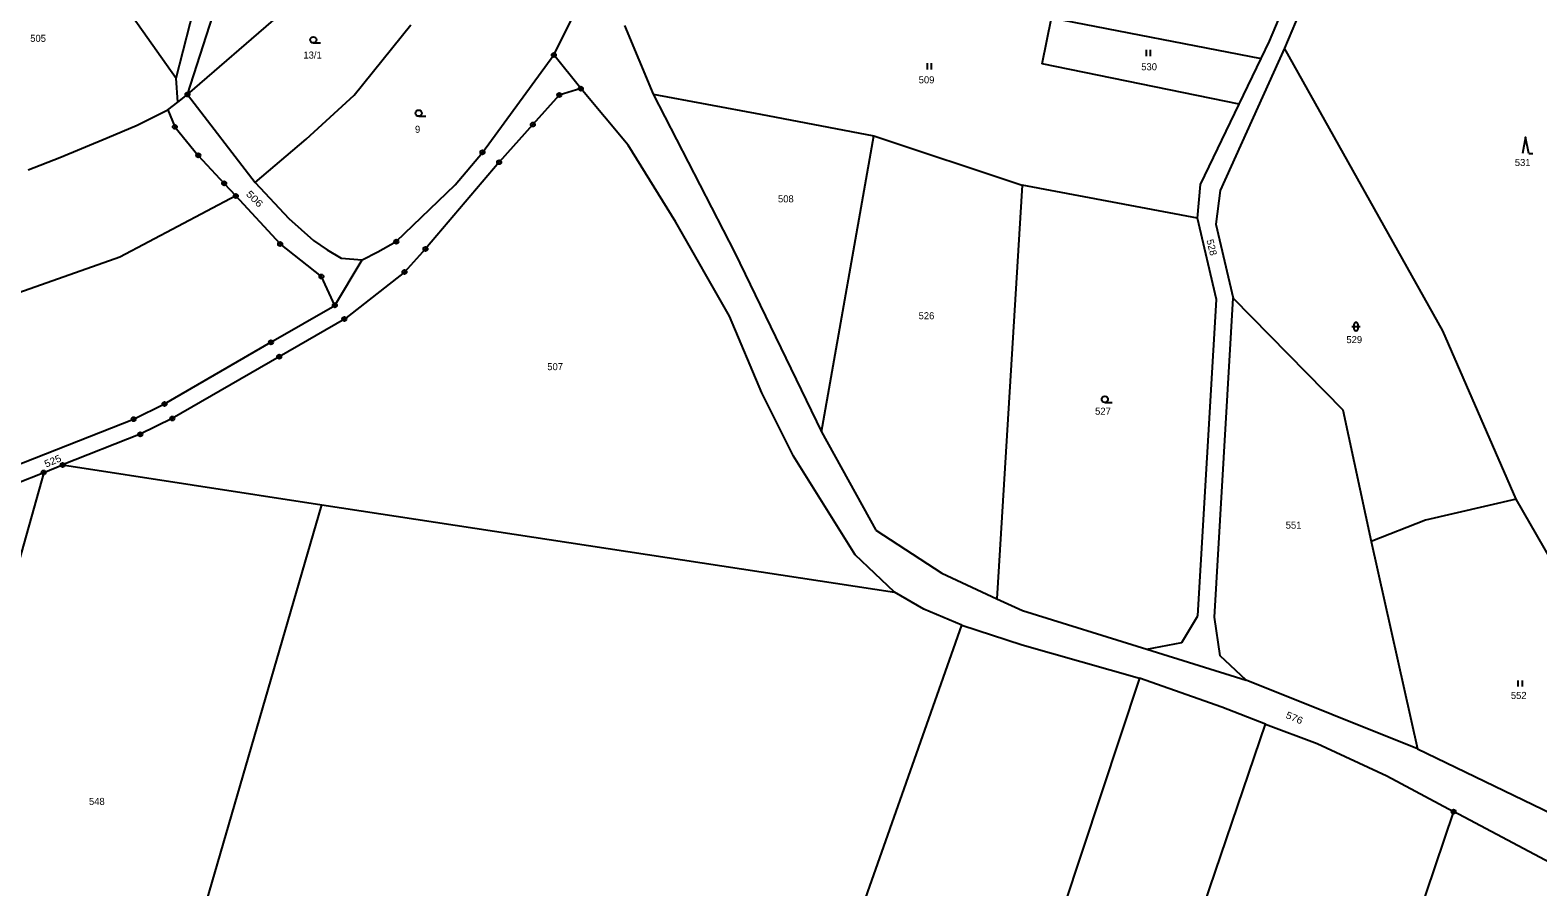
# Model space of a CAD drawing. Extents: x -719614 to -717765, y -1095834 to -1093862.
# Drawn here: x -718913.7 to -718549.9, y -1095578 to -1095371.4 of the extents above; entities that cross this region are included whole.
import ezdxf
from ezdxf.enums import TextEntityAlignment as Align

# ---------------------------------------------------------------- set-up
doc = ezdxf.new("R2010")
doc.units = 0
doc.header["$LTSCALE"] = 0.68
for name, color, linetype, lineweight in [('1', 7, 'Continuous', 25), ('3', 7, 'Continuous', 25), ('8', 7, 'Continuous', 25)]:
    doc.layers.add(name, color=color, linetype=linetype, lineweight=lineweight)
doc.layers.add('2', color=7, linetype='Continuous')

msp = doc.modelspace()

# ---------------------------------------------------------------- linework, layer by layer
at = {"layer": '1'}
for p, q in [((-718908.69, -1095340.19), (-718878.49, -1095383)), ((-718875.73, -1095386.91), (-718864.2, -1095351)), ((-718614.65, -1095374.04), (-718606.5, -1095354.9)), ((-718602.56, -1095355.86), (-718611.04, -1095375.76)), ((-718878.49, -1095383), (-718872.04, -1095357.83)), ((-718787.32, -1095377.39), (-718781.29, -1095365.38)), ((-718875.73, -1095386.91), (-718853.79, -1095367.97)), ((-718835.53, -1095387.04), (-718821.84, -1095370.12)), ((-718770.26, -1095370.31), (-718763.38, -1095386.82)), ((-718669.47, -1095379.53), (-718667.2, -1095368.41)), ((-718667.2, -1095368.41), (-718616.65, -1095378.21)), ((-718616.65, -1095378.21), (-718614.65, -1095374.04)), ((-718804.55, -1095400.87), (-718787.32, -1095377.39)), ((-718780.81, -1095385.51), (-718787.32, -1095377.39)), ((-718611.04, -1095375.76), (-718626.57, -1095410.1)), ((-718621.96, -1095389.26), (-718616.65, -1095378.21)), ((-718572.81, -1095443.92), (-718611.04, -1095375.76)), ((-718621.96, -1095389.26), (-718669.47, -1095379.53)), ((-718878.08, -1095388.77), (-718878.49, -1095383)), ((-718780.81, -1095385.51), (-718786, -1095387.04)), ((-718769.35, -1095399.14), (-718780.81, -1095385.51)), ((-718880.45, -1095390.65), (-718878.08, -1095388.77)), ((-718878.08, -1095388.77), (-718875.73, -1095386.91)), ((-718875.73, -1095386.91), (-718859.38, -1095408.13)), ((-718847.12, -1095397.66), (-718835.53, -1095387.04)), ((-718786, -1095387.04), (-718792.39, -1095394.17)), ((-718763.38, -1095386.82), (-718737.45, -1095391.68)), ((-718763.38, -1095386.82), (-718743.68, -1095425.09)), ((-718631.26, -1095408.66), (-718621.96, -1095389.26)), ((-718887.91, -1095394.28), (-718880.45, -1095390.65)), ((-718880.45, -1095390.65), (-718878.78, -1095394.72)), ((-718737.45, -1095391.68), (-718710.11, -1095396.88)), ((-718895.14, -1095397.39), (-718887.91, -1095394.28)), ((-718878.78, -1095394.72), (-718873.12, -1095401.61)), ((-718792.39, -1095394.17), (-718800.53, -1095403.26)), ((-718906.55, -1095402.14), (-718895.14, -1095397.39)), ((-718859.38, -1095408.13), (-718847.12, -1095397.66)), ((-718757.9, -1095417.72), (-718769.35, -1095399.14)), ((-718722.72, -1095468.25), (-718710.11, -1095396.88)), ((-718914.16, -1095405.09), (-718906.55, -1095402.14)), ((-718873.12, -1095401.61), (-718866.88, -1095408.36)), ((-718800.53, -1095403.26), (-718818.31, -1095424.18)), ((-718811.16, -1095408.71), (-718804.55, -1095400.87)), ((-718864.07, -1095411.4), (-718892.08, -1095426.15)), ((-718866.88, -1095408.36), (-718864.07, -1095411.4)), ((-718853.38, -1095422.98), (-718864.07, -1095411.4)), ((-718859.38, -1095408.13), (-718851.29, -1095416.82)), ((-718825.34, -1095422.41), (-718811.16, -1095408.71)), ((-718632.02, -1095416.73), (-718674.3, -1095408.79)), ((-718632.02, -1095416.73), (-718631.26, -1095408.66)), ((-718626.57, -1095410.1), (-718627.57, -1095418.19)), ((-718851.29, -1095416.82), (-718845.32, -1095422.11)), ((-718744.93, -1095440.4), (-718757.9, -1095417.72)), ((-718627.42, -1095436.36), (-718632.02, -1095416.73)), ((-718627.57, -1095418.19), (-718623.39, -1095436.01)), ((-718845.32, -1095422.11), (-718842.06, -1095424.37)), ((-718843.4, -1095430.82), (-718853.38, -1095422.98)), ((-718842.06, -1095424.37), (-718838.62, -1095426.36)), ((-718833.57, -1095426.8), (-718829.8, -1095424.89)), ((-718829.8, -1095424.89), (-718825.34, -1095422.41)), ((-718818.31, -1095424.18), (-718823.37, -1095429.75)), ((-718743.68, -1095425.09), (-718722.72, -1095468.25)), ((-718892.08, -1095426.15), (-718971.21, -1095454.09)), ((-718840.17, -1095437.78), (-718833.57, -1095426.8)), ((-718838.62, -1095426.36), (-718833.57, -1095426.8)), ((-718840.17, -1095437.78), (-718843.4, -1095430.82)), ((-718823.37, -1095429.75), (-718837.87, -1095441.08)), ((-718631.9, -1095512.66), (-718627.42, -1095436.36)), ((-718627.91, -1095513.02), (-718623.39, -1095436.01)), ((-718623.39, -1095436.01), (-718596.9, -1095463)), ((-718855.59, -1095446.7), (-718840.17, -1095437.78)), ((-718737.17, -1095458.92), (-718744.93, -1095440.4)), ((-718837.87, -1095441.08), (-718853.59, -1095450.16)), ((-718555.1, -1095484.57), (-718572.81, -1095443.92)), ((-718881.28, -1095461.56), (-718855.59, -1095446.7)), ((-718853.59, -1095450.16), (-718879.4, -1095465.08)), ((-718888.73, -1095465.23), (-718881.28, -1095461.56)), ((-718729.47, -1095474.16), (-718737.17, -1095458.92)), ((-718917.97, -1095476.77), (-718888.73, -1095465.23)), ((-718879.4, -1095465.08), (-718887.11, -1095468.89)), ((-718596.9, -1095463), (-718590.12, -1095494.76)), ((-718887.11, -1095468.89), (-718905.85, -1095476.29)), ((-718722.72, -1095468.25), (-718709.63, -1095492.03)), ((-718910.42, -1095478.1), (-718905.85, -1095476.29)), ((-718905.85, -1095476.29), (-718843.27, -1095485.87)), ((-718714.65, -1095497.99), (-718729.47, -1095474.16)), ((-718910.42, -1095478.1), (-718949.18, -1095616.11)), ((-718916.93, -1095480.67), (-718910.42, -1095478.1)), ((-718889.92, -1095646.28), (-718843.27, -1095485.87)), ((-718843.27, -1095485.87), (-718705.14, -1095506.99)), ((-718555.1, -1095484.57), (-718576.95, -1095489.6)), ((-718515.95, -1095552.63), (-718555.1, -1095484.57)), ((-718576.95, -1095489.6), (-718590.12, -1095494.76)), ((-718709.63, -1095492.03), (-718693.73, -1095502.36)), ((-718590.12, -1095494.76), (-718578.93, -1095544.76)), ((-718705.14, -1095506.99), (-718714.65, -1095497.99)), ((-718693.73, -1095502.36), (-718680.42, -1095508.56)), ((-718698.04, -1095511.07), (-718705.14, -1095506.99)), ((-718680.42, -1095508.56), (-718674.26, -1095511.42)), ((-718688.84, -1095514.91), (-718698.04, -1095511.07)), ((-718674.26, -1095511.42), (-718644.22, -1095520.71)), ((-718635.76, -1095519.11), (-718631.9, -1095512.66)), ((-718626.53, -1095522.3), (-718627.91, -1095513.02)), ((-718703.75, -1095557.1), (-718688.84, -1095514.91)), ((-718688.84, -1095514.91), (-718674.34, -1095519.63)), ((-718674.34, -1095519.63), (-718646, -1095527.74)), ((-718644.22, -1095520.71), (-718635.76, -1095519.11)), ((-718644.22, -1095520.71), (-718620.27, -1095528.22)), ((-718620.27, -1095528.22), (-718626.53, -1095522.3)), ((-718646, -1095527.74), (-718664.41, -1095583.31)), ((-718626.1, -1095534.71), (-718646, -1095527.74)), ((-718578.93, -1095544.76), (-718620.27, -1095528.22)), ((-718615.58, -1095538.8), (-718626.1, -1095534.71)), ((-718645.05, -1095625.35), (-718615.58, -1095538.8)), ((-718615.58, -1095538.8), (-718603.13, -1095543.49)), ((-718603.13, -1095543.49), (-718586.33, -1095551.23)), ((-718578.93, -1095544.76), (-718546.41, -1095560.42)), ((-718586.33, -1095551.23), (-718570.21, -1095559.91)), ((-718764.27, -1095728.35), (-718703.75, -1095557.1)), ((-718570.21, -1095559.91), (-718587.03, -1095609.31)), ((-718492.07, -1095601.38), (-718570.21, -1095559.91))]:
    msp.add_line(p, q, dxfattribs=at)
msp.add_lwpolyline([(-718710.11, -1095396.88), (-718674.3, -1095408.79), (-718680.42, -1095508.56)], dxfattribs=at)
at = {"layer": '3'}
for p, q in [((-718845.383, -1095374.49), (-718843.633, -1095374.49)), ((-718644.321, -1095377.64), (-718644.321, -1095376.14)), ((-718643.32, -1095377.64), (-718643.32, -1095376.14)), ((-718697.171, -1095380.9), (-718697.171, -1095379.4)), ((-718696.17, -1095380.9), (-718696.17, -1095379.4)), ((-718819.943, -1095392.17), (-718818.193, -1095392.17)), ((-718552.08, -1095401.18), (-718551.084, -1095401.18)), ((-718594.761, -1095442.911), (-718592.759, -1095442.911)), ((-718594.261, -1095442.411), (-718594.261, -1095443.412)), ((-718593.259, -1095443.412), (-718593.259, -1095442.411)), ((-718654.363, -1095461.18), (-718652.613, -1095461.18)), ((-718554.621, -1095529.74), (-718554.621, -1095528.24)), ((-718553.62, -1095529.74), (-718553.62, -1095528.24))]:
    msp.add_line(p, q, dxfattribs=at)
msp.add_lwpolyline([(-718552.08, -1095401.18), (-718552.83, -1095397.18), (-718553.58, -1095401.18)], dxfattribs=at)
for centre in [(-718845.3829, -1095373.7398), (-718819.9429, -1095391.4198), (-718654.3629, -1095460.4298)]:
    msp.add_circle(centre, 0.75, dxfattribs=at)
for centre, start, end in [((-718593.76, -1095442.4109), 0, 180), ((-718593.76, -1095443.4109), 180, 359.98789)]:
    msp.add_arc(centre, 0.5, start, end, dxfattribs=at)
at = {"layer": '8'}
for centre, radius in [((-718787.32, -1095377.3899), 0.5), ((-718787.32, -1095377.3899), 0.0303), ((-718780.81, -1095385.5099), 0.5), ((-718780.81, -1095385.5099), 0.0303), ((-718875.73, -1095386.9099), 0.5), ((-718875.73, -1095386.9099), 0.0303), ((-718786, -1095387.0399), 0.5), ((-718786, -1095387.0399), 0.0303), ((-718878.78, -1095394.7199), 0.5), ((-718878.78, -1095394.7199), 0.0303), ((-718792.39, -1095394.1699), 0.5), ((-718792.39, -1095394.1699), 0.0303), ((-718804.55, -1095400.8699), 0.5), ((-718873.12, -1095401.6099), 0.5), ((-718873.12, -1095401.6099), 0.0303), ((-718804.55, -1095400.8699), 0.0303), ((-718800.53, -1095403.2599), 0.5), ((-718800.53, -1095403.2599), 0.0303), ((-718866.88, -1095408.3599), 0.5), ((-718866.88, -1095408.3599), 0.0303), ((-718864.07, -1095411.3999), 0.5), ((-718864.07, -1095411.3999), 0.0303), ((-718825.34, -1095422.4099), 0.5), ((-718853.38, -1095422.9799), 0.5), ((-718853.38, -1095422.9799), 0.0303), ((-718825.34, -1095422.4099), 0.0303), ((-718818.31, -1095424.1799), 0.5), ((-718818.31, -1095424.1799), 0.0303), ((-718823.37, -1095429.7499), 0.5), ((-718843.4, -1095430.8199), 0.5), ((-718843.4, -1095430.8199), 0.0303), ((-718823.37, -1095429.7499), 0.0303), ((-718840.17, -1095437.7799), 0.5), ((-718840.17, -1095437.7799), 0.0303), ((-718837.87, -1095441.0799), 0.5), ((-718837.87, -1095441.0799), 0.0303), ((-718855.59, -1095446.6999), 0.5), ((-718855.59, -1095446.6999), 0.0303), ((-718853.59, -1095450.1599), 0.5), ((-718853.59, -1095450.1599), 0.0303), ((-718881.28, -1095461.5599), 0.5), ((-718881.28, -1095461.5599), 0.0303), ((-718888.73, -1095465.2299), 0.5), ((-718888.73, -1095465.2299), 0.0303), ((-718879.4, -1095465.0799), 0.5), ((-718879.4, -1095465.0799), 0.0303), ((-718887.11, -1095468.8899), 0.5), ((-718887.11, -1095468.8899), 0.0303), ((-718905.85, -1095476.2899), 0.5), ((-718905.85, -1095476.2899), 0.0303), ((-718910.42, -1095478.0999), 0.5), ((-718910.42, -1095478.0999), 0.0303), ((-718570.21, -1095559.9099), 0.5), ((-718570.21, -1095559.9099), 0.0303)]:
    msp.add_circle(centre, radius, dxfattribs=at)

# ---------------------------------------------------------------- texts
at = {"layer": '2'}
for s, p in [('505', (-718911.779, -1095374.215)), ('13/1', (-718845.549, -1095378.255)), ('530', (-718643.679, -1095381.072)), ('509', (-718697.389, -1095384.222)), ('9', (-718820.2, -1095396.155)), ('531', (-718553.539, -1095404.162)), ('508', (-718731.339, -1095412.942)), ('526', (-718697.409, -1095441.132)), ('529', (-718594.179, -1095446.892)), ('507', (-718787.009, -1095453.412)), ('527', (-718654.819, -1095464.162)), ('551', (-718608.819, -1095491.662)), ('552', (-718554.489, -1095532.722)), ('548', (-718897.599, -1095558.292))]:
    msp.add_text(s, height=1.7, dxfattribs=at).set_placement(p, align=Align.CENTER)
for s, rotation, width, p in [('506', 315, 1.2, (-718860.131, -1095412.692)), ('528', 284, 1.05, (-718629.3885, -1095424.0044)), ('525', 23, 1.1, (-718907.9091, -1095476.1083)), ('576', 337, 1.1, (-718608.9511, -1095538.0617))]:
    msp.add_text(s, height=1.7, rotation=rotation, dxfattribs=dict(at, width=width)).set_placement(p, align=Align.CENTER)

doc.saveas('drawing.dxf')
